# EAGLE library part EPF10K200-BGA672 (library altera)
EPF10K200 FLEX 10K family
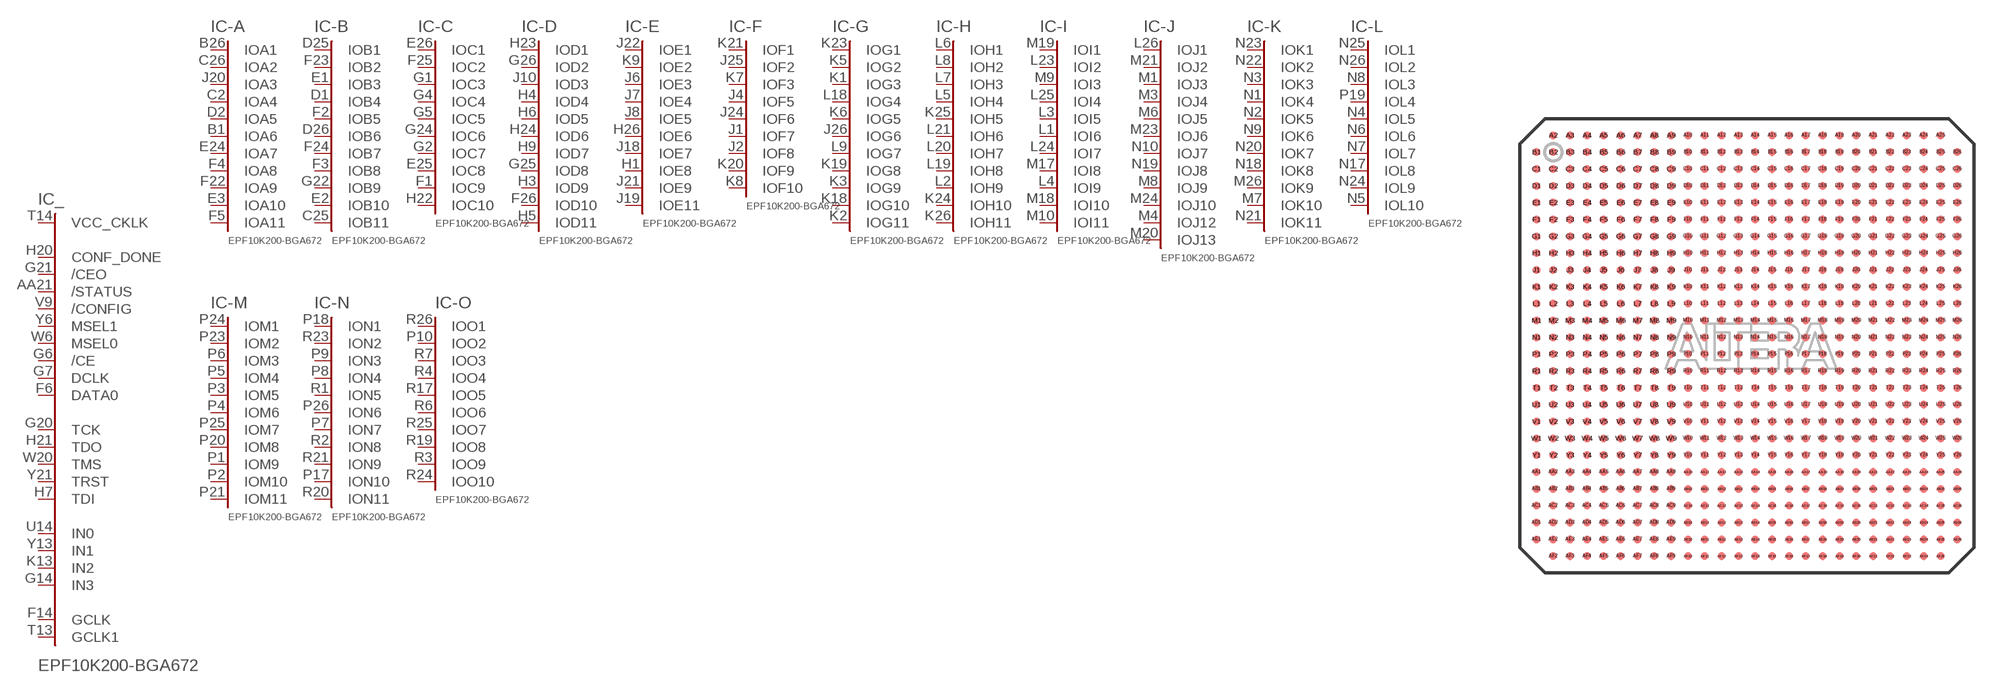
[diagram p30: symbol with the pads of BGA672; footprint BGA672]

Designator prefix IC; gates _=K200-CTR -A=A11-672 -B=B11-672 -C=C10-672 -D=D11-672 -E=E11-672 -F=F10-672 -G=G11-672 -H=H11-672 -I=I11-672 -J=J13-672 -K=K11-672 -L=L10-672 -M=M11-672 -N=N11-672 -O=O10-672 -P=P11-672 -Q=Q11-672 -R=R10-672 -S=S11-672 -T=T11-672 -U=U10-672 -V=V11-672 -W=W11-672 -X=X10-672 -1=IO44 -2=IO84 -3=IO124 -4=IO164 -5=IO204 -6=IO244 -7=IO284 -8=IO324 -9=IO364 -10=IO404 -11=IO444 -12=IO484 -13=IO524 G1=GND G2=GND G3=GND G4=GND G5=GND G6=GND G7=GND G8=GND G9=GND G10=GND G11=GND G12=GND G13=GND G14=GND G15=GND G16=GND G17=GND G18=GND G19=GND G20=GND G21=GND G22=GND G23=GND G24=GND G25=GND G26=GND G27=GND G28=GND G29=GND G30=GND G31=GND G32=GND G33=GND G34=GND G35=GND G36=GND G37=GND G38=GND G39=GND G40=GND G41=GND G42=GND G43=GND G44=GND G45=GND G46=GND G47=GND G48=GND G49=GND G50=GND G51=GND G52=GND G53=GND G54=GND G55=GND G56=GND G57=GND NC1=NC NC2=NC NC3=NC NC4=NC NC5=NC NC6=NC NC7=NC NC8=NC NC9=NC NC10=NC NC11=NC NC12=NC NC13=NC NC14=NC NC15=NC NC16=NC NC17=NC NC18=NC NC19=NC NC20=NC NC21=NC NC22=NC NC23=NC NC24=NC NC25=NC NC26=NC NC27=NC NC28=NC NC29=NC NC30=NC NC31=NC NC32=NC NC33=NC NC34=NC NC35=NC NC36=NC NC37=NC NC38=NC NC39=NC NC40=NC NC41=NC NC42=NC NC43=NC NC44=NC NC45=NC NC46=NC NC47=NC NC48=NC NC49=NC NC50=NC NC51=NC NC52=NC NC53=NC NC54=NC NC55=NC NC56=NC NC57=NC NC58=NC NC59=NC NC60=NC NC61=NC NC62=NC NC63=NC NC64=NC NC65=NC NC66=NC NC67=NC NC68=NC NC69=NC NC70=NC NC71=NC V1=VCCINT V2=VCCINT V3=VCCINT V4=VCCINT V5=VCCINT V6=VCCINT V7=VCCINT V8=VCCINT V9=VCCINT V10=VCCINT V11=VCCINT V12=VCCINT V13=VCCINT V14=VCCINT V15=VCCINT V16=VCCINT V17=VCCINT V18=VCCINT V19=VCCINT V20=VCCINT V21=VCCINT V22=VCCINT V23=VCCINT V24=VCCINT V25=VCCINT V26=VCCINT V27=VCCINT V28=VCCINT VO1=VCCIO VO2=VCCIO VO3=VCCIO VO4=VCCIO VO5=VCCIO VO6=VCCIO VO7=VCCIO VO8=VCCIO VO9=VCCIO VO10=VCCIO VO11=VCCIO VO12=VCCIO VO13=VCCIO VO14=VCCIO VO15=VCCIO VO16=VCCIO VO17=VCCIO VO18=VCCIO VO19=VCCIO VO20=VCCIO VO21=VCCIO VO22=VCCIO VO23=VCCIO VO24=VCCIO VO25=VCCIO VO26=VCCIO VO27=VCCIO VO28=VCCIO VO29=VCCIO VO30=VCCIO VO31=VCCIO

## EPF10K200-BGA672 (MPN: EPF10K200EFC672-1; OC_FARNELL: unknown; OC_NEWARK: 51R8900)  [BGA672]
A2  G17:GND  pwr
A3  -1:IO13
A4  NC36:NC  nc
A5  NC37:NC  nc
A6  NC38:NC  nc
A7  -2:IO84
A8  -2:IO83
A9  -4:IO143
A10  NC39:NC  nc
A11  NC40:NC  nc
A12  NC41:NC  nc
A13  NC42:NC  nc
A14  NC43:NC  nc
A15  NC44:NC  nc
A16  NC45:NC  nc
A17  NC46:NC  nc
A18  NC47:NC  nc
A19  NC48:NC  nc
A20  NC49:NC  nc
A21  NC50:NC  nc
A22  NC51:NC  nc
A23  NC52:NC  nc
A24  NC53:NC  nc
A25  G18:GND  pwr
AA1  -V:IOV11
AA2  -V:IOV9
AA3  -V:IOV5
AA4  -W:IOW3
AA5  -X:IOX9
AA6  -X:IOX4
AA7  -1:IO34
AA8  -2:IO61
AA9  -3:IO121
AA10  -4:IO134
AA11  -5:IO174
AA12  -6:IO224
AA13  G1:GND  pwr
AA14  -7:IO271
AA15  -8:IO311
AA16  -9:IO351
AA17  -11:IO411
AA18  -11:IO431
AA19  -11:IO434
AA20  -V:IOV8
AA21  _:/STATUS  in
AA22  G2:GND  pwr
AA23  V1:VCC  pwr
AA24  -X:IOX1
AA25  -W:IOW11
AA26  VO1:VCCIO  pwr
AB1  -V:IOV7
AB2  -V:IOV3
AB3  G3:GND  pwr
AB4  G4:GND  pwr
AB5  G5:GND  pwr
AB6  -2:IO64
AB7  -2:IO74
AB8  -2:IO71
AB9  -3:IO104
AB10  V2:VCC  pwr
AB11  -5:IO184
AB12  -6:IO221
AB13  -7:IO263
AB14  -7:IO282
AB15  -8:IO314
AB16  -9:IO344
AB17  -10:IO391
AB18  -11:IO424
AB19  -11:IO414
AB20  -12:IO461
AB21  -12:IO471
AB22  -X:IOX6
AB23  G6:GND  pwr
AB24  G7:GND  pwr
AB25  -X:IOX7
AB26  -W:IOW4
AC1  -W:IOW9
AC2  -W:IOW5
AC3  G8:GND  pwr
AC4  -X:IOX5
AC5  -1:IO14
AC6  -1:IO24
AC7  -2:IO82
AC8  G9:GND  pwr
AC9  -4:IO131
AC10  -4:IO144
AC11  -5:IO181
AC12  -6:IO231
AC13  -7:IO264
AC14  V3:VCC  pwr
AC15  -8:IO301
AC16  -9:IO334
AC17  -10:IO384
AC18  -10:IO402
AC19  -12:IO451
AC20  -11:IO441
AC21  -12:IO454
AC22  -12:IO481
AC23  -13:IO494
AC24  G10:GND  pwr
AC25  -X:IOX2
AC26  -X:IOX10
AD1  -W:IOW7
AD2  -W:IOW2
AD3  -X:IOX3
AD4  -1:IO31
AD5  -1:IO41
AD6  -2:IO52
AD7  -1:IO44
AD8  -3:IO91
AD9  -3:IO114
AD10  -4:IO161
AD11  -5:IO191
AD12  -6:IO234
AD13  G11:GND  pwr
AD14  -7:IO274
AD15  VO2:VCCIO  pwr
AD16  -9:IO341
AD17  -10:IO374
AD18  G12:GND  pwr
AD19  -11:IO421
AD20  -12:IO464
AD21  -12:IO474
AD22  -12:IO484
AD23  -13:IO514
AD24  -13:IO524
AD25  -13:IO521
AD26  -13:IO503
AE1  -X:IOX8
AE2  G13:GND  pwr
AE3  -1:IO21
AE4  NC1:NC  nc
AE5  NC2:NC  nc
AE6  NC3:NC  nc
AE7  NC4:NC  nc
AE8  NC5:NC  nc
AE9  NC6:NC  nc
AE10  NC7:NC  nc
AE11  NC8:NC  nc
AE12  NC9:NC  nc
AE13  -7:IO253
AE14  NC10:NC  nc
AE15  NC11:NC  nc
AE16  NC12:NC  nc
AE17  NC13:NC  nc
AE18  -10:IO394
AE19  NC14:NC  nc
AE20  NC15:NC  nc
AE21  NC16:NC  nc
AE22  NC17:NC  nc
AE23  NC18:NC  nc
AE24  -13:IO511
AE25  G14:GND  pwr
AE26  -13:IO491
AF2  G15:GND  pwr
AF3  -1:IO11
AF4  NC19:NC  nc
AF5  NC20:NC  nc
AF6  NC21:NC  nc
AF7  NC22:NC  nc
AF8  NC23:NC  nc
AF9  NC24:NC  nc
AF10  NC25:NC  nc
AF11  -5:IO194
AF12  NC26:NC  nc
AF13  NC27:NC  nc
AF14  NC28:NC  nc
AF15  NC29:NC  nc
AF16  NC30:NC  nc
AF17  -10:IO373
AF18  NC31:NC  nc
AF19  -11:IO444
AF20  NC32:NC  nc
AF21  NC33:NC  nc
AF22  -13:IO504
AF23  NC34:NC  nc
AF24  NC35:NC  nc
AF25  G16:GND  pwr
B1  -A:IOA6
B2  G19:GND  pwr
B3  -1:IO23
B4  NC54:NC  nc
B5  NC55:NC  nc
B6  NC56:NC  nc
B7  NC57:NC  nc
B8  NC58:NC  nc
B9  NC59:NC  nc
B10  NC60:NC  nc
B11  NC61:NC  nc
B12  NC62:NC  nc
B13  NC63:NC  nc
B14  -7:IO284
B15  -8:IO312
B16  NC64:NC  nc
B17  -10:IO383
B18  -10:IO393
B19  NC65:NC  nc
B20  NC66:NC  nc
B21  NC67:NC  nc
B22  NC68:NC  nc
B23  NC69:NC  nc
B24  NC70:NC  nc
B25  G20:GND  pwr
B26  -A:IOA1
C1  NC71:NC  nc
C2  -A:IOA4
C3  G21:GND  pwr
C4  -1:IO33
C5  -1:IO43
C6  -1:IO12
C7  -2:IO73
C8  VO3:VCCIO  pwr
C9  -3:IO122
C10  G22:GND  pwr
C11  -5:IO193
C12  -6:IO232
C13  -7:IO261
C14  -7:IO283
C15  VO4:VCCIO  pwr
C16  -9:IO342
C17  -10:IO392
C18  -11:IO412
C19  -12:IO463
C20  -12:IO453
C21  -12:IO472
C22  -12:IO482
C23  -13:IO523
C24  G23:GND  pwr
C25  -B:IOB11
C26  -A:IOA2
D1  -B:IOB4
D2  -A:IOA5
D3  G24:GND  pwr
D4  G25:GND  pwr
D5  -1:IO22
D6  -1:IO32
D7  VO5:VCCIO  pwr
D8  -2:IO62
D9  -3:IO113
D10  -4:IO162
D11  -5:IO182
D12  -6:IO213
D13  -7:IO252
D14  -8:IO293
D15  -8:IO322
D16  -9:IO352
D17  -10:IO382
D18  -11:IO413
D19  G26:GND  pwr
D20  -12:IO483
D21  -13:IO493
D22  -13:IO501
D23  G27:GND  pwr
D24  G28:GND  pwr
D25  -B:IOB1
D26  -B:IOB6
E1  -B:IOB3
E2  -B:IOB10
E3  -A:IOA10
E4  G29:GND  pwr
E5  -2:IO54
E6  -2:IO63
E7  -1:IO42
E8  -2:IO53
E9  -3:IO103
E10  -4:IO153
E11  -5:IO172
E12  -6:IO222
E13  V4:VCC  pwr
E14  -7:IO273
E15  -8:IO323
E16  -9:IO363
E17  V5:VCC  pwr
E18  -11:IO432
E19  -11:IO443
E20  -12:IO473
E21  -12:IO462
E22  -13:IO513
E23  G30:GND  pwr
E24  -A:IOA7
E25  -C:IOC8
E26  -C:IOC1
F1  -C:IOC9
F2  -B:IOB5
F3  -B:IOB8
F4  -A:IOA8
F5  -A:IOA11
F6  _:DATA0  in
F7  -3:IO102
F8  -2:IO72
F9  -4:IO132
F10  -4:IO133
F11  -5:IO183
F12  -6:IO212
F13  -7:IO251
F14  _:GCLK  in
F15  -9:IO333
F16  -9:IO364
F17  -10:IO403
F18  -11:IO423
F19  -12:IO452
F20  -13:IO512
F21  -13:IO522
F22  -A:IOA9
F23  -B:IOB2
F24  -B:IOB7
F25  -C:IOC2
F26  -D:IOD10
G1  -C:IOC3
G2  -C:IOC7
G3  VO6:VCCIO  pwr
G4  -C:IOC4
G5  -C:IOC5
G6  _:/CE  in
G7  _:DCLK  in
G8  -3:IO92
G9  -3:IO123
G10  -4:IO152
G11  -5:IO173
G12  -5:IO202
G13  -6:IO243
G14  _:IN3  in
G15  -9:IO332
G16  -10:IO372
G17  -9:IO354
G18  -11:IO442
G19  -13:IO502
G20  _:TCK
G21  _:/CEO  in
G22  -B:IOB9
G23  G31:GND  pwr
G24  -C:IOC6
G25  -D:IOD8
G26  -D:IOD2
H1  -E:IOE8
H2  V6:VCC  pwr
H3  -D:IOD9
H4  -D:IOD4
H5  -D:IOD11
H6  -D:IOD5
H7  _:TDI
H8  -3:IO112
H9  -D:IOD7
H10  -3:IO93
H11  -4:IO163
H12  -5:IO203
H13  -6:IO233
H14  -7:IO272
H15  -8:IO313
H16  -10:IO371
H17  -11:IO422
H18  -11:IO433
H19  -13:IO492
H20  _:CONF_DONE  in
H21  _:TDO
H22  -C:IOC10
H23  -D:IOD1
H24  -D:IOD6
H25  V7:VCC  pwr
H26  -E:IOE6
J1  -F:IOF7
J2  -F:IOF8
J3  VO7:VCCIO  pwr
J4  -F:IOF5
J5  G32:GND  pwr
J6  -E:IOE3
J7  -E:IOE4
J8  -E:IOE5
J9  -4:IO142
J10  -D:IOD3
J11  -5:IO192
J12  -6:IO223
J13  -7:IO262
J14  -8:IO292
J15  -8:IO302
J16  -10:IO401
J17  VO8:VCCIO  pwr
J18  -E:IOE7
J19  -E:IOE11
J20  -A:IOA3
J21  -E:IOE9
J22  -E:IOE1
J23  G33:GND  pwr
J24  -F:IOF6
J25  -F:IOF2
J26  -G:IOG6
K1  -G:IOG3
K2  -G:IOG11
K3  -G:IOG9
K4  G34:GND  pwr
K5  -G:IOG2
K6  -G:IOG5
K7  -F:IOF3
K8  -F:IOF10
K9  -E:IOE2
K10  G35:GND  pwr
K11  VO9:VCCIO  pwr
K12  -6:IO242
K13  _:IN2  in
K14  -8:IO303
K15  -9:IO343
K16  V8:VCC  pwr
K17  G36:GND  pwr
K18  -G:IOG10
K19  -G:IOG8
K20  -F:IOF9
K21  -F:IOF1
K22  VO10:VCCIO  pwr
K23  -G:IOG1
K24  -H:IOH10
K25  -H:IOH5
K26  -H:IOH11
L1  -I:IOI6
L2  -H:IOH9
L3  -I:IOI5
L4  -I:IOI9
L5  -H:IOH4
L6  -H:IOH1
L7  -H:IOH3
L8  -H:IOH2
L9  -G:IOG7
L10  V9:VCC  pwr
L11  G37:GND  pwr
L12  V10:VCC  pwr
L13  VO11:VCCIO  pwr
L14  V11:VCC  pwr
L15  VO12:VCCIO  pwr
L16  G38:GND  pwr
L17  V12:VCC  pwr
L18  -G:IOG4
L19  -H:IOH8
L20  -H:IOH7
L21  -H:IOH6
L22  G39:GND  pwr
L23  -I:IOI2
L24  -I:IOI7
L25  -I:IOI4
L26  -J:IOJ1
M1  -J:IOJ3
M2  V13:VCC  pwr
M3  -J:IOJ4
M4  -J:IOJ12
M5  G40:GND  pwr
M6  -J:IOJ5
M7  -K:IOK10
M8  -J:IOJ9
M9  -I:IOI3
M10  -I:IOI11
M11  VO13:VCCIO  pwr
M12  G41:GND  pwr
M13  VO14:VCCIO  pwr
M14  G42:GND  pwr
M15  G43:GND  pwr
M16  VO15:VCCIO  pwr
M17  -I:IOI8
M18  -I:IOI10
M19  -I:IOI1
M20  -J:IOJ13
M21  -J:IOJ2
M22  VO16:VCCIO  pwr
M23  -J:IOJ6
M24  -J:IOJ10
M25  V14:VCC  pwr
M26  -K:IOK9
N1  -K:IOK4
N2  -K:IOK5
N3  -K:IOK3
N4  -L:IOL5
N5  -L:IOL10
N6  -L:IOL6
N7  -L:IOL7
N8  -L:IOL3
N9  -K:IOK6
N10  -J:IOJ7
N11  V15:VCC  pwr
N12  V16:VCC  pwr
N13  G44:GND  pwr
N14  G45:GND  pwr
N15  V17:VCC  pwr
N16  VO17:VCCIO  pwr
N17  -L:IOL8
N18  -K:IOK8
N19  -J:IOJ8
N20  -K:IOK7
N21  -K:IOK11
N22  -K:IOK2
N23  -K:IOK1
N24  -L:IOL9
N25  -L:IOL1
N26  -L:IOL2
P1  -M:IOM9
P2  -M:IOM10
P3  -M:IOM5
P4  -M:IOM6
P5  -M:IOM4
P6  -M:IOM3
P7  -N:ION7
P8  -N:ION4
P9  -N:ION3
P10  -O:IOO2
P11  VO18:VCCIO  pwr
P12  V18:VCC  pwr
P13  G46:GND  pwr
P14  G47:GND  pwr
P15  V19:VCC  pwr
P16  V20:VCC  pwr
P17  -N:ION10
P18  -N:ION1
P19  -L:IOL4
P20  -M:IOM8
P21  -M:IOM11
P22  G48:GND  pwr
P23  -M:IOM2
P24  -M:IOM1
P25  -M:IOM7
P26  -N:ION6
R1  -N:ION5
R2  -N:ION8
R3  -O:IOO9
R4  -O:IOO4
R5  VO19:VCCIO  pwr
R6  -O:IOO6
R7  -O:IOO3
R8  -P:IOP6
R9  -P:IOP2
R10  -Q:IOQ8
R11  VO20:VCCIO  pwr
R12  G49:GND  pwr
R13  VO21:VCCIO  pwr
R14  V21:VCC  pwr
R15  G50:GND  pwr
R16  VO22:VCCIO  pwr
R17  -O:IOO5
R18  -P:IOP1
R19  -O:IOO8
R20  -N:ION11
R21  -N:ION9
R22  VO23:VCCIO  pwr
R23  -N:ION2
R24  -O:IOO10
R25  -O:IOO7
R26  -O:IOO1
T1  -P:IOP9
T2  V22:VCC  pwr
T3  -P:IOP3
T4  -P:IOP4
T5  -P:IOP7
T6  -Q:IOQ9
T7  -Q:IOQ6
T8  -R:IOR7
T9  -R:IOR5
T10  V23:VCC  pwr
T11  G51:GND  pwr
T12  V24:VCC  pwr
T13  _:GCLK1  in
T14  _:VCC_CKLK  pas
T15  VO24:VCCIO  pwr
T16  G52:GND  pwr
T17  V25:VCC  pwr
T18  -R:IOR10
T19  -Q:IOQ1
T20  -Q:IOQ10
T21  -P:IOP8
T22  -P:IOP10
T23  -P:IOP5
T24  -P:IOP11
T25  V26:VCC  pwr
T26  -Q:IOQ5
U1  -Q:IOQ3
U2  -Q:IOQ2
U3  VO25:VCCIO  pwr
U4  -R:IOR9
U5  -R:IOR4
U6  -R:IOR8
U7  -S:IOS5
U8  -S:IOS3
U9  -S:IOS4
U10  G53:GND  pwr
U11  VO26:VCCIO  pwr
U12  -5:IO204
U13  -6:IO241
U14  _:IN0  in
U15  -8:IO304
U16  V27:VCC  pwr
U17  G54:GND  pwr
U18  -R:IOR6
U19  -S:IOS11
U20  -R:IOR1
U21  -Q:IOQ11
U22  -Q:IOQ7
U23  -R:IOR3
U24  G55:GND  pwr
U25  -Q:IOQ4
U26  -R:IOR2
V1  -S:IOS9
V2  -S:IOS7
V3  G56:GND  pwr
V4  -S:IOS8
V5  VO27:VCCIO  pwr
V6  -T:IOT9
V7  -T:IOT3
V8  -U:IOU3
V9  _:/CONFIG  in
V10  -4:IO141
V11  -4:IO154
V12  -5:IO201
V13  -6:IO244
V14  -8:IO291
V15  -9:IO331
V16  -10:IO381
V17  VO28:VCCIO  pwr
V18  -S:IOS1
V19  -S:IOS10
V20  -V:IOV6
V21  -T:IOT10
V22  -S:IOS6
V23  -S:IOS2
V24  VO29:VCCIO  pwr
V25  -T:IOT6
V26  -T:IOT11
W1  -T:IOT2
W2  -T:IOT7
W3  -T:IOT4
W4  -U:IOU7
W5  -U:IOU4
W6  _:MSEL0  in
W7  -2:IO51
W8  -3:IO101
W9  -3:IO111
W10  -3:IO124
W11  -4:IO164
W12  -6:IO214
W13  -7:IO254
W14  -8:IO294
W15  -8:IO321
W16  -9:IO362
W17  -9:IO361
W18  -T:IOT8
W19  -U:IOU6
W20  _:TMS
W21  -V:IOV10
W22  -U:IOU2
W23  -T:IOT1
W24  -U:IOU10
W25  -U:IOU1
W26  -U:IOU9
Y1  -U:IOU8
Y2  VO30:VCCIO  pwr
Y3  -U:IOU5
Y4  -V:IOV4
Y5  G57:GND  pwr
Y6  _:MSEL1  in
Y7  V28:VCC  pwr
Y8  -2:IO81
Y9  -3:IO94
Y10  -4:IO151
Y11  -5:IO171
Y12  -6:IO211
Y13  _:IN1  in
Y14  -7:IO281
Y15  -8:IO324
Y16  -9:IO353
Y17  -10:IO404
Y18  -T:IOT5
Y19  -V:IOV2
Y20  -W:IOW8
Y21  _:TRST
Y22  -W:IOW1
Y23  -W:IOW6
Y24  VO31:VCCIO  pwr
Y25  -V:IOV1
Y26  -W:IOW10

## Footprint BGA672 (pad centres in mm)
Ball Grid Array
smd 0.45 x 0.45: A2 -11.5,12.5; A3 -10.5,12.5; A4 -9.5,12.5; A5 -8.5,12.5; A6 -7.5,12.5; A7 -6.5,12.5; A8 -5.5,12.5; A9 -4.5,12.5; A10 -3.5,12.5; A11 -2.5,12.5; A12 -1.5,12.5; A13 -0.5,12.5; A14 0.5,12.5; A15 1.5,12.5; A16 2.5,12.5; A17 3.5,12.5; A18 4.5,12.5; A19 5.5,12.5; A20 6.5,12.5; A21 7.5,12.5; A22 8.5,12.5; A23 9.5,12.5; A24 10.5,12.5; A25 11.5,12.5; AA1 -12.5,-7.5; AA2 -11.5,-7.5; AA3 -10.5,-7.5; AA4 -9.5,-7.5; AA5 -8.5,-7.5; AA6 -7.5,-7.5; AA7 -6.5,-7.5; AA8 -5.5,-7.5; AA9 -4.5,-7.5; AA10 -3.5,-7.5; AA11 -2.5,-7.5; AA12 -1.5,-7.5; AA13 -0.5,-7.5; AA14 0.5,-7.5; AA15 1.5,-7.5; AA16 2.5,-7.5; AA17 3.5,-7.5; AA18 4.5,-7.5; AA19 5.5,-7.5; AA20 6.5,-7.5; AA21 7.5,-7.5; AA22 8.5,-7.5; AA23 9.5,-7.5; AA24 10.5,-7.5; AA25 11.5,-7.5; AA26 12.5,-7.5; AB1 -12.5,-8.5; AB2 -11.5,-8.5; AB3 -10.5,-8.5; AB4 -9.5,-8.5; AB5 -8.5,-8.5; AB6 -7.5,-8.5; AB7 -6.5,-8.5; AB8 -5.5,-8.5; AB9 -4.5,-8.5; AB10 -3.5,-8.5; AB11 -2.5,-8.5; AB12 -1.5,-8.5; AB13 -0.5,-8.5; AB14 0.5,-8.5; AB15 1.5,-8.5; AB16 2.5,-8.5; AB17 3.5,-8.5; AB18 4.5,-8.5; AB19 5.5,-8.5; AB20 6.5,-8.5; AB21 7.5,-8.5; AB22 8.5,-8.5; AB23 9.5,-8.5; AB24 10.5,-8.5; AB25 11.5,-8.5; AB26 12.5,-8.5; AC1 -12.5,-9.5; AC2 -11.5,-9.5; AC3 -10.5,-9.5; AC4 -9.5,-9.5; AC5 -8.5,-9.5; AC6 -7.5,-9.5; AC7 -6.5,-9.5; AC8 -5.5,-9.5; AC9 -4.5,-9.5; AC10 -3.5,-9.5; AC11 -2.5,-9.5; AC12 -1.5,-9.5; AC13 -0.5,-9.5; AC14 0.5,-9.5; AC15 1.5,-9.5; AC16 2.5,-9.5; AC17 3.5,-9.5; AC18 4.5,-9.5; AC19 5.5,-9.5; AC20 6.5,-9.5; AC21 7.5,-9.5; AC22 8.5,-9.5; AC23 9.5,-9.5; AC24 10.5,-9.5; AC25 11.5,-9.5; AC26 12.5,-9.5; AD1 -12.5,-10.5; AD2 -11.5,-10.5; AD3 -10.5,-10.5; AD4 -9.5,-10.5; AD5 -8.5,-10.5; AD6 -7.5,-10.5; AD7 -6.5,-10.5; AD8 -5.5,-10.5; AD9 -4.5,-10.5; AD10 -3.5,-10.5; AD11 -2.5,-10.5; AD12 -1.5,-10.5; AD13 -0.5,-10.5; AD14 0.5,-10.5; AD15 1.5,-10.5; AD16 2.5,-10.5; AD17 3.5,-10.5; AD18 4.5,-10.5; AD19 5.5,-10.5; AD20 6.5,-10.5; AD21 7.5,-10.5; AD22 8.5,-10.5; AD23 9.5,-10.5; AD24 10.5,-10.5; AD25 11.5,-10.5; AD26 12.5,-10.5; AE1 -12.5,-11.5; AE2 -11.5,-11.5; AE3 -10.5,-11.5; AE4 -9.5,-11.5; AE5 -8.5,-11.5; AE6 -7.5,-11.5; AE7 -6.5,-11.5; AE8 -5.5,-11.5; AE9 -4.5,-11.5; AE10 -3.5,-11.5; AE11 -2.5,-11.5; AE12 -1.5,-11.5; AE13 -0.5,-11.5; AE14 0.5,-11.5; AE15 1.5,-11.5; AE16 2.5,-11.5; AE17 3.5,-11.5; AE18 4.5,-11.5; AE19 5.5,-11.5; AE20 6.5,-11.5; AE21 7.5,-11.5; AE22 8.5,-11.5; AE23 9.5,-11.5; AE24 10.5,-11.5; AE25 11.5,-11.5; AE26 12.5,-11.5; AF2 -11.5,-12.5; AF3 -10.5,-12.5; AF4 -9.5,-12.5; AF5 -8.5,-12.5; AF6 -7.5,-12.5; AF7 -6.5,-12.5; AF8 -5.5,-12.5; AF9 -4.5,-12.5; AF10 -3.5,-12.5; AF11 -2.5,-12.5; AF12 -1.5,-12.5; AF13 -0.5,-12.5; AF14 0.5,-12.5; AF15 1.5,-12.5; AF16 2.5,-12.5; AF17 3.5,-12.5; AF18 4.5,-12.5; AF19 5.5,-12.5; AF20 6.5,-12.5; AF21 7.5,-12.5; AF22 8.5,-12.5; AF23 9.5,-12.5; AF24 10.5,-12.5; AF25 11.5,-12.5; B1 -12.5,11.5; B2 -11.5,11.5; B3 -10.5,11.5; B4 -9.5,11.5; B5 -8.5,11.5; B6 -7.5,11.5; B7 -6.5,11.5; B8 -5.5,11.5; B9 -4.5,11.5; B10 -3.5,11.5; B11 -2.5,11.5; B12 -1.5,11.5; B13 -0.5,11.5; B14 0.5,11.5; B15 1.5,11.5; B16 2.5,11.5; B17 3.5,11.5; B18 4.5,11.5; B19 5.5,11.5; B20 6.5,11.5; B21 7.5,11.5; B22 8.5,11.5; B23 9.5,11.5; B24 10.5,11.5; B25 11.5,11.5; B26 12.5,11.5; C1 -12.5,10.5; C2 -11.5,10.5; C3 -10.5,10.5; C4 -9.5,10.5; C5 -8.5,10.5; C6 -7.5,10.5; C7 -6.5,10.5; C8 -5.5,10.5; C9 -4.5,10.5; C10 -3.5,10.5; C11 -2.5,10.5; C12 -1.5,10.5; C13 -0.5,10.5; C14 0.5,10.5; C15 1.5,10.5; C16 2.5,10.5; C17 3.5,10.5; C18 4.5,10.5; C19 5.5,10.5; C20 6.5,10.5; C21 7.5,10.5; C22 8.5,10.5; C23 9.5,10.5; C24 10.5,10.5; C25 11.5,10.5; C26 12.5,10.5; D1 -12.5,9.5; D2 -11.5,9.5; D3 -10.5,9.5; D4 -9.5,9.5; D5 -8.5,9.5; D6 -7.5,9.5; D7 -6.5,9.5; D8 -5.5,9.5; D9 -4.5,9.5; D10 -3.5,9.5; D11 -2.5,9.5; D12 -1.5,9.5; D13 -0.5,9.5; D14 0.5,9.5; D15 1.5,9.5; D16 2.5,9.5; D17 3.5,9.5; D18 4.5,9.5; D19 5.5,9.5; D20 6.5,9.5; D21 7.5,9.5; D22 8.5,9.5; D23 9.5,9.5; D24 10.5,9.5; D25 11.5,9.5; D26 12.5,9.5; E1 -12.5,8.5; E2 -11.5,8.5; E3 -10.5,8.5; E4 -9.5,8.5; E5 -8.5,8.5; E6 -7.5,8.5; E7 -6.5,8.5; E8 -5.5,8.5; E9 -4.5,8.5; E10 -3.5,8.5; E11 -2.5,8.5; E12 -1.5,8.5; E13 -0.5,8.5; E14 0.5,8.5; E15 1.5,8.5; E16 2.5,8.5; E17 3.5,8.5; E18 4.5,8.5; E19 5.5,8.5; E20 6.5,8.5; E21 7.5,8.5; E22 8.5,8.5; E23 9.5,8.5; E24 10.5,8.5; E25 11.5,8.5; E26 12.5,8.5; F1 -12.5,7.5; F2 -11.5,7.5; F3 -10.5,7.5; F4 -9.5,7.5; F5 -8.5,7.5; F6 -7.5,7.5; F7 -6.5,7.5; F8 -5.5,7.5; F9 -4.5,7.5; F10 -3.5,7.5; F11 -2.5,7.5; F12 -1.5,7.5; F13 -0.5,7.5; F14 0.5,7.5; F15 1.5,7.5; F16 2.5,7.5; F17 3.5,7.5; F18 4.5,7.5; F19 5.5,7.5; F20 6.5,7.5; F21 7.5,7.5; F22 8.5,7.5; F23 9.5,7.5; F24 10.5,7.5; F25 11.5,7.5; F26 12.5,7.5; G1 -12.5,6.5; G2 -11.5,6.5; G3 -10.5,6.5; G4 -9.5,6.5; G5 -8.5,6.5; G6 -7.5,6.5; G7 -6.5,6.5; G8 -5.5,6.5; G9 -4.5,6.5; G10 -3.5,6.5; G11 -2.5,6.5; G12 -1.5,6.5; G13 -0.5,6.5; G14 0.5,6.5; G15 1.5,6.5; G16 2.5,6.5; G17 3.5,6.5; G18 4.5,6.5; G19 5.5,6.5; G20 6.5,6.5; G21 7.5,6.5; G22 8.5,6.5; G23 9.5,6.5; G24 10.5,6.5; G25 11.5,6.5; G26 12.5,6.5; H1 -12.5,5.5; H2 -11.5,5.5; H3 -10.5,5.5; H4 -9.5,5.5; H5 -8.5,5.5; H6 -7.5,5.5; H7 -6.5,5.5; H8 -5.5,5.5; H9 -4.5,5.5; H10 -3.5,5.5; H11 -2.5,5.5; H12 -1.5,5.5; H13 -0.5,5.5; H14 0.5,5.5; H15 1.5,5.5; H16 2.5,5.5; H17 3.5,5.5; H18 4.5,5.5; H19 5.5,5.5; H20 6.5,5.5; H21 7.5,5.5; H22 8.5,5.5; H23 9.5,5.5; H24 10.5,5.5; H25 11.5,5.5; H26 12.5,5.5; J1 -12.5,4.5; J2 -11.5,4.5; J3 -10.5,4.5; J4 -9.5,4.5; J5 -8.5,4.5; J6 -7.5,4.5; J7 -6.5,4.5; J8 -5.5,4.5; J9 -4.5,4.5; J10 -3.5,4.5; J11 -2.5,4.5; J12 -1.5,4.5; J13 -0.5,4.5; J14 0.5,4.5; J15 1.5,4.5; J16 2.5,4.5; J17 3.5,4.5; J18 4.5,4.5; J19 5.5,4.5; J20 6.5,4.5; J21 7.5,4.5; J22 8.5,4.5; J23 9.5,4.5; J24 10.5,4.5; J25 11.5,4.5; J26 12.5,4.5; K1 -12.5,3.5; K2 -11.5,3.5; K3 -10.5,3.5; K4 -9.5,3.5; K5 -8.5,3.5; K6 -7.5,3.5; K7 -6.5,3.5; K8 -5.5,3.5; K9 -4.5,3.5; K10 -3.5,3.5; K11 -2.5,3.5; K12 -1.5,3.5; K13 -0.5,3.5; K14 0.5,3.5; K15 1.5,3.5; K16 2.5,3.5; K17 3.5,3.5; K18 4.5,3.5; K19 5.5,3.5; K20 6.5,3.5; K21 7.5,3.5; K22 8.5,3.5; K23 9.5,3.5; K24 10.5,3.5; K25 11.5,3.5; K26 12.5,3.5; L1 -12.5,2.5; L2 -11.5,2.5; L3 -10.5,2.5; L4 -9.5,2.5; L5 -8.5,2.5; L6 -7.5,2.5; L7 -6.5,2.5; L8 -5.5,2.5; L9 -4.5,2.5; L10 -3.5,2.5; L11 -2.5,2.5; L12 -1.5,2.5; L13 -0.5,2.5; L14 0.5,2.5; L15 1.5,2.5; L16 2.5,2.5; L17 3.5,2.5; L18 4.5,2.5; L19 5.5,2.5; L20 6.5,2.5; L21 7.5,2.5; L22 8.5,2.5; L23 9.5,2.5; L24 10.5,2.5; L25 11.5,2.5; L26 12.5,2.5; M1 -12.5,1.5; M2 -11.5,1.5; M3 -10.5,1.5; M4 -9.5,1.5; M5 -8.5,1.5; M6 -7.5,1.5; M7 -6.5,1.5; M8 -5.5,1.5; M9 -4.5,1.5; M10 -3.5,1.5; M11 -2.5,1.5; M12 -1.5,1.5; M13 -0.5,1.5; M14 0.5,1.5; M15 1.5,1.5; M16 2.5,1.5; M17 3.5,1.5; M18 4.5,1.5; M19 5.5,1.5; M20 6.5,1.5; M21 7.5,1.5; M22 8.5,1.5; M23 9.5,1.5; M24 10.5,1.5; M25 11.5,1.5; M26 12.5,1.5; N1 -12.5,0.5; N2 -11.5,0.5; N3 -10.5,0.5; N4 -9.5,0.5; N5 -8.5,0.5; N6 -7.5,0.5; N7 -6.5,0.5; N8 -5.5,0.5; N9 -4.5,0.5; N10 -3.5,0.5; N11 -2.5,0.5; N12 -1.5,0.5; N13 -0.5,0.5; N14 0.5,0.5; N15 1.5,0.5; N16 2.5,0.5; N17 3.5,0.5; N18 4.5,0.5; N19 5.5,0.5; N20 6.5,0.5; N21 7.5,0.5; N22 8.5,0.5; N23 9.5,0.5; N24 10.5,0.5; N25 11.5,0.5; N26 12.5,0.5; P1 -12.5,-0.5; P2 -11.5,-0.5; P3 -10.5,-0.5; P4 -9.5,-0.5; P5 -8.5,-0.5; P6 -7.5,-0.5; P7 -6.5,-0.5; P8 -5.5,-0.5; P9 -4.5,-0.5; P10 -3.5,-0.5; P11 -2.5,-0.5; P12 -1.5,-0.5; P13 -0.5,-0.5; P14 0.5,-0.5; P15 1.5,-0.5; P16 2.5,-0.5; P17 3.5,-0.5; P18 4.5,-0.5; P19 5.5,-0.5; P20 6.5,-0.5; P21 7.5,-0.5; P22 8.5,-0.5; P23 9.5,-0.5; P24 10.5,-0.5; P25 11.5,-0.5; P26 12.5,-0.5; R1 -12.5,-1.5; R2 -11.5,-1.5; R3 -10.5,-1.5; R4 -9.5,-1.5; R5 -8.5,-1.5; R6 -7.5,-1.5; R7 -6.5,-1.5; R8 -5.5,-1.5; R9 -4.5,-1.5; R10 -3.5,-1.5; R11 -2.5,-1.5; R12 -1.5,-1.5; R13 -0.5,-1.5; R14 0.5,-1.5; R15 1.5,-1.5; R16 2.5,-1.5; R17 3.5,-1.5; R18 4.5,-1.5; R19 5.5,-1.5; R20 6.5,-1.5; R21 7.5,-1.5; R22 8.5,-1.5; R23 9.5,-1.5; R24 10.5,-1.5; R25 11.5,-1.5; R26 12.5,-1.5; T1 -12.5,-2.5; T2 -11.5,-2.5; T3 -10.5,-2.5; T4 -9.5,-2.5; T5 -8.5,-2.5; T6 -7.5,-2.5; T7 -6.5,-2.5; T8 -5.5,-2.5; T9 -4.5,-2.5; T10 -3.5,-2.5; T11 -2.5,-2.5; T12 -1.5,-2.5; T13 -0.5,-2.5; T14 0.5,-2.5; T15 1.5,-2.5; T16 2.5,-2.5; T17 3.5,-2.5; T18 4.5,-2.5; T19 5.5,-2.5; T20 6.5,-2.5; T21 7.5,-2.5; T22 8.5,-2.5; T23 9.5,-2.5; T24 10.5,-2.5; T25 11.5,-2.5; T26 12.5,-2.5; U1 -12.5,-3.5; U2 -11.5,-3.5; U3 -10.5,-3.5; U4 -9.5,-3.5; U5 -8.5,-3.5; U6 -7.5,-3.5; U7 -6.5,-3.5; U8 -5.5,-3.5; U9 -4.5,-3.5; U10 -3.5,-3.5; U11 -2.5,-3.5; U12 -1.5,-3.5; U13 -0.5,-3.5; U14 0.5,-3.5; U15 1.5,-3.5; U16 2.5,-3.5; U17 3.5,-3.5; U18 4.5,-3.5; U19 5.5,-3.5; U20 6.5,-3.5; U21 7.5,-3.5; U22 8.5,-3.5; U23 9.5,-3.5; U24 10.5,-3.5; U25 11.5,-3.5; U26 12.5,-3.5; V1 -12.5,-4.5; V2 -11.5,-4.5; V3 -10.5,-4.5; V4 -9.5,-4.5; V5 -8.5,-4.5; V6 -7.5,-4.5; V7 -6.5,-4.5; V8 -5.5,-4.5; V9 -4.5,-4.5; V10 -3.5,-4.5; V11 -2.5,-4.5; V12 -1.5,-4.5; V13 -0.5,-4.5; V14 0.5,-4.5; V15 1.5,-4.5; V16 2.5,-4.5; V17 3.5,-4.5; V18 4.5,-4.5; V19 5.5,-4.5; V20 6.5,-4.5; V21 7.5,-4.5; V22 8.5,-4.5; V23 9.5,-4.5; V24 10.5,-4.5; V25 11.5,-4.5; V26 12.5,-4.5; W1 -12.5,-5.5; W2 -11.5,-5.5; W3 -10.5,-5.5; W4 -9.5,-5.5; W5 -8.5,-5.5; W6 -7.5,-5.5; W7 -6.5,-5.5; W8 -5.5,-5.5; W9 -4.5,-5.5; W10 -3.5,-5.5; W11 -2.5,-5.5; W12 -1.5,-5.5; W13 -0.5,-5.5; W14 0.5,-5.5; W15 1.5,-5.5; W16 2.5,-5.5; W17 3.5,-5.5; W18 4.5,-5.5; W19 5.5,-5.5; W20 6.5,-5.5; W21 7.5,-5.5; W22 8.5,-5.5; W23 9.5,-5.5; W24 10.5,-5.5; W25 11.5,-5.5; W26 12.5,-5.5; Y1 -12.5,-6.5; Y2 -11.5,-6.5; Y3 -10.5,-6.5; Y4 -9.5,-6.5; Y5 -8.5,-6.5; Y6 -7.5,-6.5; Y7 -6.5,-6.5; Y8 -5.5,-6.5; Y9 -4.5,-6.5; Y10 -3.5,-6.5; Y11 -2.5,-6.5; Y12 -1.5,-6.5; Y13 -0.5,-6.5; Y14 0.5,-6.5; Y15 1.5,-6.5; Y16 2.5,-6.5; Y17 3.5,-6.5; Y18 4.5,-6.5; Y19 5.5,-6.5; Y20 6.5,-6.5; Y21 7.5,-6.5; Y22 8.5,-6.5; Y23 9.5,-6.5; Y24 10.5,-6.5; Y25 11.5,-6.5; Y26 12.5,-6.5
